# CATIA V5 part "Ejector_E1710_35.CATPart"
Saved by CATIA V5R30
Part number: Vyhazovac_7x160_11
Nomenclature: E1710/7x160
Description: MEUSBURGER
Property "Material": "1.221"
Publications: "__DrillHole", "Base"
Bounding box of the stored display mesh (mm): x -5.992 to 5.992, y -5.992 to 5.992, z 0 to 152
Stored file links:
  E:\Bakalarka\Model\Forma_v7\Ejector_E1710_35.CATPart
  E:\dev\MoldDesign\intel_a\startup\components\MoldCatalog\Ejector\Meusburger\Ejector_E1710\TableE1710.txt
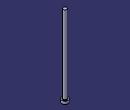
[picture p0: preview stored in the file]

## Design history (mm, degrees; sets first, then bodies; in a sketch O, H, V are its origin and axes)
Parameters
  Ref = "E1710/7x160" {design table}
  D1 = 7 mm {design table}
  D3 = 12 mm {design table}
  L = 160 mm {design table}
  L3 = 5 mm {design table}
  R = 0.5 mm {design table}
  k_d3 = 13 mm {design table}
  k_d1 = 7.2 mm {design table}
  k_F = 0.5 mm {design table}
  kl = 17 mm {design table}
  Mat = "1.221" {design table}
  HeatTreat = "ISO6751" {design table}
  Offset_Parting = 10 mm
  Anti_Rotation = "Normal"
  Anti_Rotation_D = 4 mm
  Anti_Rotation_D_Icut = 4 mm
  Add_Length_L = 1.3377 mm
  Add_Length_D3 = 0 mm
  SupplierRef = "Meusburger 2017"
  BmpRef = "F_MldEjectorD1"
  DrillHole_Length = 225 mm
  ValidationTest = false
  Anti_Rotation_D_min = 4 mm {= OffSet_D1 /2}
  Anti_Rotation_D_max = 5.925 mm {= D3/2-0.075mm}
  Anti_Rotation_D_ref = 4 mm {= Anti_Rotation_D}
  Anti_Rotation_D_Icut_ref = 4 mm {= Anti_Rotation_D_Icut}
  Anti_Rotation_Ref_Icut = 2.3246 mm
  Offset_L = 20 mm
  D = 7 mm {= D1}
  OffSet_D1 = 8 mm {= D1+2*R}
  OffSet_D3 = 13 mm {= D3+1mm}
  XG_Split = 135 mm
  YG_Split = -10 mm
  ZG_Split = -198 mm
  DirX_Split = 0 mm
  DirY_Split = 0 mm
  DirZ_Split = 1 mm
Set1 "BaseBody"
  Point1 "Base": (0, 0, 0)
  Plane1: type Offset, RefPlane xy-plane, Offset 225 {= DrillHole_Length}, reversed
  Sketch1 "Sketch.2" on xy-plane, origin (0, 0, 0), H (1, 0, 0), V (0, 1, 0)
    point P1 (-0.46, 1.1623)
    point P2 (0.46, 1.1623)
    construction line L1 (-0.46, 1.1623) -> (0.46, 1.1623)
    point P3 (0.46, -1.1623)
    line L2 (0.46, -1.1623) -> (0.46, 1.1623)
    point P4 (-0.46, -1.1623)
    construction line L3 (0.46, -1.1623) -> (-0.46, -1.1623)
    line L4 (-0.46, 1.1623) -> (-0.46, -1.1623)
    point P5 (-0.21, 1.1623)
    arc A1 centre (-0.21, 1.1623) radius 0.25 from (-0.21, 1.4123) to (-0.46, 1.1623) ccw
    point P7 (0.21, 1.1623)
    point P8 (0.21, 1.4123)
    arc A2 centre (0.21, 1.1623) radius 0.25 from (0.46, 1.1623) to (0.21, 1.4123) ccw
    line L5 (-0.21, 1.4123) -> (0.21, 1.4123)
    point P9 (-0.46, -1.1623)
    arc A3 centre (-0.21, -1.1623) radius 0.25 from (-0.46, -1.1623) to (-0.21, -1.4123) ccw
    point P11 (0.21, -1.4123)
    line L6 (-0.21, -1.4123) -> (0.21, -1.4123)
    point P12 (0.46, -1.1623)
    arc A4 centre (0.21, -1.1623) radius 0.25 from (0.21, -1.4123) to (0.46, -1.1623) ccw
    point P14 (-0.46, 1.1623)
    point P15 (-0.46, -1.1623)
    point P16 (0.46, 1.1623)
    point P17 (0.46, -1.1623)
    reference projected circle E1 centre (0, 0) radius 1.25 from edge [face of Shaft1 from Sketch2.L3 | face of Shaft1 from Sketch2.L4]
    reference projected circle E2 centre (0, 0) radius 1.25 from edge [face of Shaft1 from Sketch2.L3 | face of Shaft1 from Sketch2.L4]
    reference projected circle E3 centre (0, 0) radius 1.25 from edge [face of Shaft1 from Sketch2.L3 | face of Shaft1 from Sketch2.L4]
    reference projected circle E4 centre (0, 0) radius 1.25 from edge [face of Shaft1 from Sketch2.L3 | face of Shaft1 from Sketch2.L4]
    point P18 (-0.46, -1.1623)
    point P19 (-0.21, -1.4123)
    point P20 (0.21, -1.4123)
    point P21 (0.46, -1.1623)
    point P22 (-0.21, -1.4123)
    point P23 (0.21, -1.4123)
    distance P14 P15 = 2.3246 (reference)
    distance P16 P17 = 2.3246 (reference)
    distance L1 P14 = 0 (reference)
    radius A1 = 3.5
    distance L4 V = 4.01
    distance L2 V = 5.935
    distance L5 L6 = 12
    horizontal: L1 H, L3 H, L5 H
    vertical: L2 V, L4 V
    coincidence: P5 L1, P7 L1, P3 P12, P14 L4, P15 L4, P16 L2, P17 L2, P14 E1, P15 E2, P16 E3, P17 E4, P3 P21, P4 P18, P20 P23, P19 P22
    tangency: A1 L4, A2 L2, A2 L5, A1 L5
    symmetry: P1 P9 H, A1 A3 H, P8 P11 H, L5 L6 H, P2 P12 H, A2 A4 H
  DatumSurface1
Body1 "PartBody" (main body)
  Sketch2 "Sketch.1" on zx-plane, origin (0, 0, 0), H (-1, 0, 0), V (0, 0, 1)
    point P1 (0, 160)
    line L1 (3.5, 160) -> (0, 160)
    line L2 (3.5, 5) -> (3.5, 160)
    line L3 (6, 5) -> (3.5, 5)
    line L4 (6, 0) -> (6, 5)
    point P5 (0, 0)
    line L5 (0, 0) -> (6, 0)
    point P6 (0, 160)
    axis line L6 (0, 160) -> (0, 0)
    point P7 (0, 0)
    point P8 (3.5, 5)
    point P9 (3.5, 5)
    line L7 (0, 160) -> (0, 0)
    distance L5 L3 = 5 {= L3}
    distance L5 L1 = 160 {= L}
    distance L2 L6 = 3.5 {= D1 /2}
    distance L4 L6 = 6 {= D3 /2}
    coincidence: L6 P5, P1 L6, L5 H, L6 V, P7 O, P6 P1, P8 P9
    vertical: L2 V, L7 V
    horizontal: L1 H
  Shaft1 "Shaft.1": profile Sketch2, axis Sketch2.L6, angle 360
  Pocket1 "Pocket.1": profile Sketch1, direction (0, 0, 1), length 6, outer side, deactivated
  Pocket2 "Pocket.2": profile Sketch1, direction (0, 0, 1), length 6, outer side, deactivated
  Fillet1: radius 0.5 {= R}, on edge [face of Shaft1 from Sketch2.L2 | face of Shaft1 from Sketch2.L3]
  Pocket3: profile face of Shaft1 from Sketch2.L1, direction along face of Shaft1 from Sketch2.L1 reversed, up to face of DatumSurface1
Body2 "__DrillHole"
  Sketch3 "Sketch.3" on face of Shaft1, origin (0, 0, 0), H (1, 0, 0), V (0, -1, 0)
    point P1 (0, 0)
    reference projected point E1 (0, 0) from Point1
    coincidence: E1 P1
  Hole1 "Hole.1": placed by Sketch3, at (0, 0, 0) direction (0, 0, 1), diameter 8 {= OffSet_D1}, depth 140 {= L-Offset_L}
  Sketch4 "Sketch.4" on face of Shaft1, origin (0, 0, 0), H (1, 0, 0), V (0, -1, 0)
    point P1 (0, 0)
    reference projected point E1 (0, 0) from Point1
    coincidence: E1 P1
  Hole2 "Hole.2": placed by Sketch4, at (0, 0, 0) direction (0, 0, 1), diameter 7 {= D1}, depth 160 {= L}
  Sketch5 "Sketch.5" on face of Shaft1 from Sketch2.L3, origin (0, 0, 5), H (1, 0, 0), V (0, 1, 0)
    point P1 (0, 0)
    reference projected point E1 (0, 0) from Point1
    coincidence: E1 P1
  Hole3 "Hole.3": placed by Sketch5, at (0, 0, 5) direction (0, 0, -1), diameter 13 {= OffSet_D3}, depth 230 {= L3 +DrillHole_Length}
  Chamfer1: length 0.5 {= k_F}, angle 45, on edge [face of Hole1 | face of Hole3]
  Body3 "__Body.1"
    Pocket4 "Pocket.3": profile Sketch1, direction (0, 0, -1), length 225, opposite side length 5, deactivated
  Assemble1: tool Body3
  Chamfer2: length 0.5 {= k_F}, angle 45, on edge [start face of Pocket4 | face of Hole1], deactivated
  Body4 "__Body.2"
    Pocket5 "Pocket.4": profile Sketch1, direction (0, 0, -1), length 225, opposite side length 5, deactivated
  Assemble2: tool Body4
  Chamfer3: length 0.5 {= k_F}, angle 45, on edge [start face of Pocket5 | face of Hole1], deactivated
Relations
  design table "TableE1710", configuration 278, drives Ref, D1, D3, L, L3, R, k_d3, k_d1, k_F, kl, Mat, HeatTreat
  Offset_L = 20mm (deactivated)
  rule "Cut_Head_rule":
    let sketch_cut (length)
    let PartBody_Pocket_Sketch (Boolean)
    let I_PartBody_Pocket (Boolean)
    let D_PartBody_Pocket (Boolean)
    let N_DrillHole_Hole (Boolean)
    let N_DrillHole_Hole_Sketch (Boolean)
    let I_DrillHole_Pocket (Boolean)
    let D_DrillHole_Pocket (Boolean)
    /* --------------------------------------------------------------------------------------*/
    if Anti_Rotation =="Normal"
    {
    	sketch_cut=Anti_Rotation_D_max
    	PartBody_Pocket_Sketch = false
    	I_PartBody_Pocket = false
    	D_PartBody_Pocket = false
    	N_DrillHole_Hole = true
    	N_DrillHole_Hole_Sketch = true
    	I_DrillHole_Pocket = false
    	D_DrillHole_Pocket = false
    	Chamfer1.Activity= true
    	Chamfer2.Activity= false
    	Chamfer3.Activity= false
    }
    if Anti_Rotation == "I_Cut"
    {
    	sketch_cut=Anti_Rotation_D_Icut_ref
    	PartBody_Pocket_Sketch = true
    	I_PartBody_Pocket = true
    	D_PartBody_Pocket = false
    	N_DrillHole_Hole = false
    	N_DrillHole_Hole_Sketch = false
    	I_DrillHole_Pocket = true
    	D_DrillHole_Pocket = false
    	Chamfer1.Activity= false
    	Chamfer2.Activity= true
    	Chamfer3.Activity= false
    }
    if Anti_Rotation =="D_Cut"
    {
    	sketch_cut=Anti_Rotation_D_max
    	PartBody_Pocket_Sketch = true
    	I_PartBody_Pocket = false
    	D_PartBody_Pocket = true
    	N_DrillHole_Hole = false
    	N_DrillHole_Hole_Sketch = false
    	I_DrillHole_Pocket = false
    	D_DrillHole_Pocket = true
    	Chamfer1.Activity= false
    	Chamfer2.Activity= false
    	Chamfer3.Activity= true
    }
    /* --------------------------------------------------------------------------------------*/
    Sketch1.distance(L2 V) = sketch_cut+0.01mm
    Sketch1.distance(L4 V) =Anti_Rotation_D_ref+0.01mm
    Sketch1.radius(A1) =D/2
    Pocket4.FirstLimit.Depth = DrillHole_Length
    Pocket5.FirstLimit.Depth = DrillHole_Length
    Pocket1.FirstLimit.Depth = L3+1mm
    Pocket2.FirstLimit.Depth = L3+1mm
    Pocket4.SecondLimit.Depth = L3
    Pocket5.SecondLimit.Depth =L3
    Pocket1.Activity = I_PartBody_Pocket
    Pocket2.Activity = D_PartBody_Pocket
    Sketch1.Activity =PartBody_Pocket_Sketch
    Hole3.Activity= N_DrillHole_Hole
    Sketch5.Activity = N_DrillHole_Hole_Sketch
    Pocket4.Activity = I_DrillHole_Pocket
    Pocket5.Activity  = D_DrillHole_Pocket
  rule "Anti_Rotation_Icut_constrain":
    let Ref1(length)
    let Ref2(length)
    let Ref3(length)
    let Diam1(length)
    let Diam2(length)
    let Add_Length_Lmin (length)
    Ref1=Sketch1.distance(P14 P15)
    Ref2=Sketch1.distance(P16 P17)
    Diam1=D
    Diam2=D3
    /* --------------------------------------------------------------------*/
    if Ref1 >Ref2
    	Anti_Rotation_Ref_Icut = Ref1
    else
    	Anti_Rotation_Ref_Icut  =Ref2
    Add_Length_D3 .InferiorRange=Anti_Rotation_Ref_Icut /2+Diam1/2 -Diam2/2
    if Add_Length_D3 .InferiorRange<0mm
    	Add_Length_D3 .InferiorRange=0mm
    if ValidationTest == "true"
    	Ref3   = 2*Add_Length_L +Anti_Rotation_Ref_Icut  +2*Diam1/2
    else
    	Ref3  =Diam2+2*Add_Length_D3
    if Ref3 <Diam2
    {
    	Ref3 =Diam2
    }
    /* --------------------------------------------------------------------*/
    Sketch1.distance(L5 L6) = Ref3
    Add_Length_L .InferiorRange=Diam2/2-Anti_Rotation_Ref_Icut/2-Diam1/2
    Add_Length_Lmin=Diam2/2-Anti_Rotation_Ref_Icut/2-Diam1/2
    if Add_Length_Lmin<0mm
    	Add_Length_L .InferiorRange=0mm
    else
    	Add_Length_L .InferiorRange=Add_Length_Lmin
